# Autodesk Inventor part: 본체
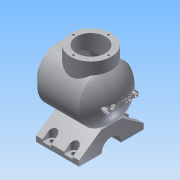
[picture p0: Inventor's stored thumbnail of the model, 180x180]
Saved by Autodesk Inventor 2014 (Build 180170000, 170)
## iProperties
Created: 2017-04
Part Number: 본체
Material: 알루미늄 6061
Document SubType Name: Modeling
Designer: SCD-A14
Density: 2.71 g/cm^3
Appearance: 알루미늄 - 평지
Mass: 1597.51 g
Surface Area: 1040.89 cm^2
Volume: 589.486 cm^3
Author: SCD-A14
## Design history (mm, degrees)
sketch "스케치1"
  geometry: L1 (0, 0)-(0, 38); L2 (0, 38)-(12, 38); L3 (12, 38)-(12, 50); L4 (12, 50)-(89.811, 50); L5 (120, 38)-(120, 0); L6 (0, 0)-(120, 0); L7 (0, 27)-(22, 27); L8 (22, 27)-(22, 40); L9 (22, 40)-(87.212, 40); A1 r 56.5 centre (63.5, 0) between (120, 0) and (89.811, 50); A2 r 46.5 centre (63.5, 0) between (110, 0) and (87.212, 40)
  constraints: 18 end point, 5 perpendicular, 4 point on circle, 3 parallel, 3 point on line, 2 centre point, 1 coincident, 1 horizontal alignment, 1 tangent
  dimensions: "d1" = 38 distance of L1.start L1.end; "d2" = 12 distance of L1.end L2.end; "d4" = 56.5 radius of A1; "d6" = 50 distance between parallel lines of L4 L6; "d7" = 108 distance from line of L5.end L3; "d8" = 54 diameter of L7 L6; "d9" = 80 diameter of L9 L6; "d11" = 22 distance of L7.start L7.end; "d12" = 46.5 radius of A2
revolve "회전1" sketch "스케치1" stored, may be unused: angle "d13" = 90 deg
node "작업 평면1"
sketch "스케치2"
  geometry: C1 r 27 at (62, 0); C2 r 38 at (62, 0); 1 further point
  constraints: 2 centre point, 1 coincident, 1 horizontal alignment
  dimensions: "d15" = 27 radius of C1; "d16" = 38 radius of C2; "d17" = 62 distance of C1.centre point (0, 0)
extrude "돌출1" join sketch "스케치2" stored distance "d18" = 10; taper "d19" = 0 deg
sketch "스케치3"
  geometry: C1 r 27 at (0, 0) reference; C2 r 38 at (0, 0) reference; C3 r 27 at (0, 0); 1 further point
  constraints: 1 centre point, 1 coincident, 1 concentric
extrude "돌출2" cut sketch "스케치3" stored distance "d20" = 10; taper "d21" = 0 deg
node "작업 평면3"
sketch "스케치4"
  geometry: L1 (0, -43.393)-(0, -64); L2 (-18, -82)-(-60, -82); L3 (-60, -82)-(-60, -72); L4 (-60, -72)-(-19.145, -43.393); L5 (-19.145, -43.393)-(0, -43.393); C1 r 50 at (0, 0) reference; A1 r 18 centre (0, -82) between (0, -64) and (-18, -82); 2 further points
  constraints: 10 end point, 2 parallel, 2 point on circle, 1 centre point, 1 coincident, 1 perpendicular, 1 vertical, 1 vertical alignment
  dimensions: "d23" = 10 distance of L2.end L3.end; "d24" = 55 deg angle of L3 L4; "d25" = 60 distance between parallel lines of L1 L3; "d26" = 82 distance from line of L2 point (0, 0); "d27" = 19.14456 distance of L4.end L1.start; "d28" = 18 radius of A1; "d29" = 20.60728 distance of L1.start L1.end; "d30" = 42 distance of L2.start L2.end
extrude "돌출3" join sketch "스케치4" stored distance "d31" = 80; taper "d32" = 0 deg
node "작업 평면4"
sketch "스케치5"
  geometry: L1 (0, -1.145)-(0, -42) reference; L2 (80, -42)-(80, -3.584) reference; L3 (80, -3.584)-(10.189, -3.584) reference; L4 (80, -42)-(80, -3.584) reference; L5 (80, -42)-(0, -42) reference; L6 (0, -1.145)-(0, -42) reference; L7 (5.795, -1.145)-(0, -1.145) reference; L8 (12, -42)-(12, -32); L9 (28, -42)-(28, -32); A1 r 8 centre (20, -32) between (28, -32) and (12, -32); 2 further points; 1 other entity
  constraints: 4 end point, 2 point on circle, 2 point on line, 2 tangent, 1 centre point, 1 parallel, 1 vertical, 1 other
  dimensions: "d34" = 8 radius of A1; "d35" = 20 distance from line of L1 A1.centre; "d36" = 10 distance from line of L5 A1.centre
extrude "돌출4" cut sketch "스케치5" distance "d37" = 40; taper "d39" = 0 deg; dims "d38" = 4, "d40" = 0
sketch "스케치6"
  geometry: C1 r 4 at (-20, -32); A1 r 8 centre (-20, -32) between (-12, -32) and (-28, -32) reference; 1 further point
  constraints: 1 centre point, 1 coincident
  dimensions: "d41" = 4 radius of C1
extrude "돌출5" cut sketch "스케치6" distance "d42" = 40; taper "d43" = 0 deg
sketch "스케치7"
  geometry: C1 r 27 at (0, 0) reference; 2 further points
  constraints: 1 vertical alignment
  dimensions: "d47" = 32.5 distance of C1.centre point (0, 32.5)
hole "구멍1" sketch "스케치7" at (0, 32.5) diameter "d48" = 3.242; stored, may be unused: countersink angle "d52" = 90 deg, drill point angle "d54" = 118 deg; dims "d49" = 8, "d50" = 4, "d51" = 2, "d53" = 10
sketch "스케치8"
  geometry: C1 r 27 at (0, 0) reference; 1 further point
  dimensions: "d58" = 0 vertical distance of C1.centre point (32.5, 0); "d59" = 32.5 distance of point (32.5, 0) C1.centre
hole "구멍2" sketch "스케치8" at (32.5, 0) diameter "d60" = 3.242; stored, may be unused: countersink angle "d64" = 90 deg, drill point angle "d66" = 118 deg; dims "d61" = 8, "d62" = 4, "d63" = 2, "d65" = 10
node "작업 평면7"
sketch "스케치11"
  geometry: 2 further points
  constraints: 1 other
  dimensions: "d75" = 0 distance of point (0, 0) point (0, 0); "d76" = 0 distance of point (0, 0) point (0, 0)
extrude "돌출6" join sketch "스케치11" stored distance "d77" = 10; taper "d78" = 0 deg
node "솔리드1"
mirror "대칭1"
pattern_linear "직사각형 패턴1"
mirror "대칭2"
pattern_circular "원형 패턴1" dims angle "d56" = 360 deg
pattern_circular "원형 패턴2" dims angle "d68" = 360 deg
node "투영된 루프1"
other parameters: "d5" = 46.5, "d14" = 65, "d74" = 120.5
